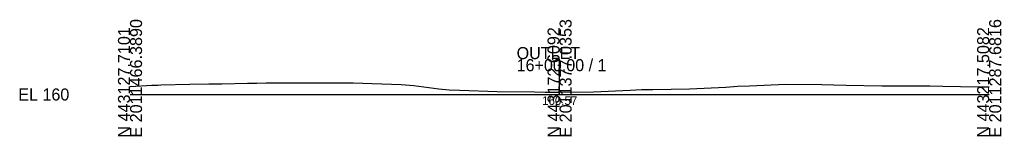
# Model space of a CAD drawing. Extents: x -26 to 1203, y -15 to 9526.
# Drawn here: x -25.7 to 202.8, y 5990.3 to 6017.3 of the extents above; entities that cross this region are included whole.
import ezdxf

# ---------------------------------------------------------------- set-up
doc = ezdxf.new("R2010")
doc.units = 0
for name, color, linetype in [('Exist Cross Section Cell', 7, 'Continuous'), ('Exist XS Center Line Elevation Label', 7, 'Continuous'), ('Exist XS Ground Line', 7, 'Continuous')]:
    doc.layers.add(name, color=color, linetype=linetype)

msp = doc.modelspace()

# ---------------------------------------------------------------- linework, layer by layer
at = {"layer": 'Exist Cross Section Cell'}
for p, q in [((100, 6000), (100, 6008.2)), ((0, 6000), (100, 6000)), ((100, 6000), (200, 6000))]:
    msp.add_line(p, q, dxfattribs=at)
at = {"layer": 'Exist XS Ground Line'}
msp.add_lwpolyline([(0, 6001.87), (5.1, 6002.17), (6.46, 6002.19), (7.15, 6002.2), (13.91, 6002.38), (18.34, 6002.49), (21.36, 6002.48), (27.37, 6002.63), (29.53, 6002.66), (31.72, 6002.68), (40.72, 6002.73), (49.64, 6002.71), (51.92, 6002.72), (58.61, 6002.5), (63.11, 6002.32), (66.05, 6002.08), (71.92, 6001.34), (74.3, 6001.07), (76.71, 6000.99), (85.49, 6000.72), (94.19, 6000.58), (96.68, 6000.52), (99.2, 6000.56), (100, 6000.57), (107.87, 6000.63), (116.46, 6001.02), (119.07, 6001.14), (121.7, 6001.15), (130.26, 6001.28), (138.73, 6001.72), (141.45, 6001.91), (144.19, 6002.02), (152.64, 6002.41), (161.01, 6002.3), (163.83, 6002.27), (166.68, 6002.19), (175.02, 6002.02), (183.28, 6002), (186.21, 6001.98), (189.18, 6001.94), (197.41, 6001.77), (200, 6001.77)], dxfattribs=at)

# ---------------------------------------------------------------- texts
at = {"layer": 'Exist Cross Section Cell'}
for s, p in [('E 2011466.3890', (2.8, 5990)), ('E 2011377.0353', (102.8, 5990)), ('E 2011287.6816', (202.8, 5990)), ('N 443127.7101', (0, 5990)), ('N 443172.6092', (100, 5990)), ('N 443217.5082', (200, 5990))]:
    msp.add_text(s, height=2.8, rotation=90, dxfattribs=at).set_placement(p)
for s, p in [('OUTLET', (90, 6008.2)), ('16+00.00 / 1', (90, 6005.4)), ('EL 160', (-26, 5998.6))]:
    msp.add_text(s, height=2.8, dxfattribs=at).set_placement(p)
at = {"layer": 'Exist XS Center Line Elevation Label'}
msp.add_text('160.57', height=2, dxfattribs=at).set_placement((95.94, 5997.57))

doc.saveas('drawing.dxf')
